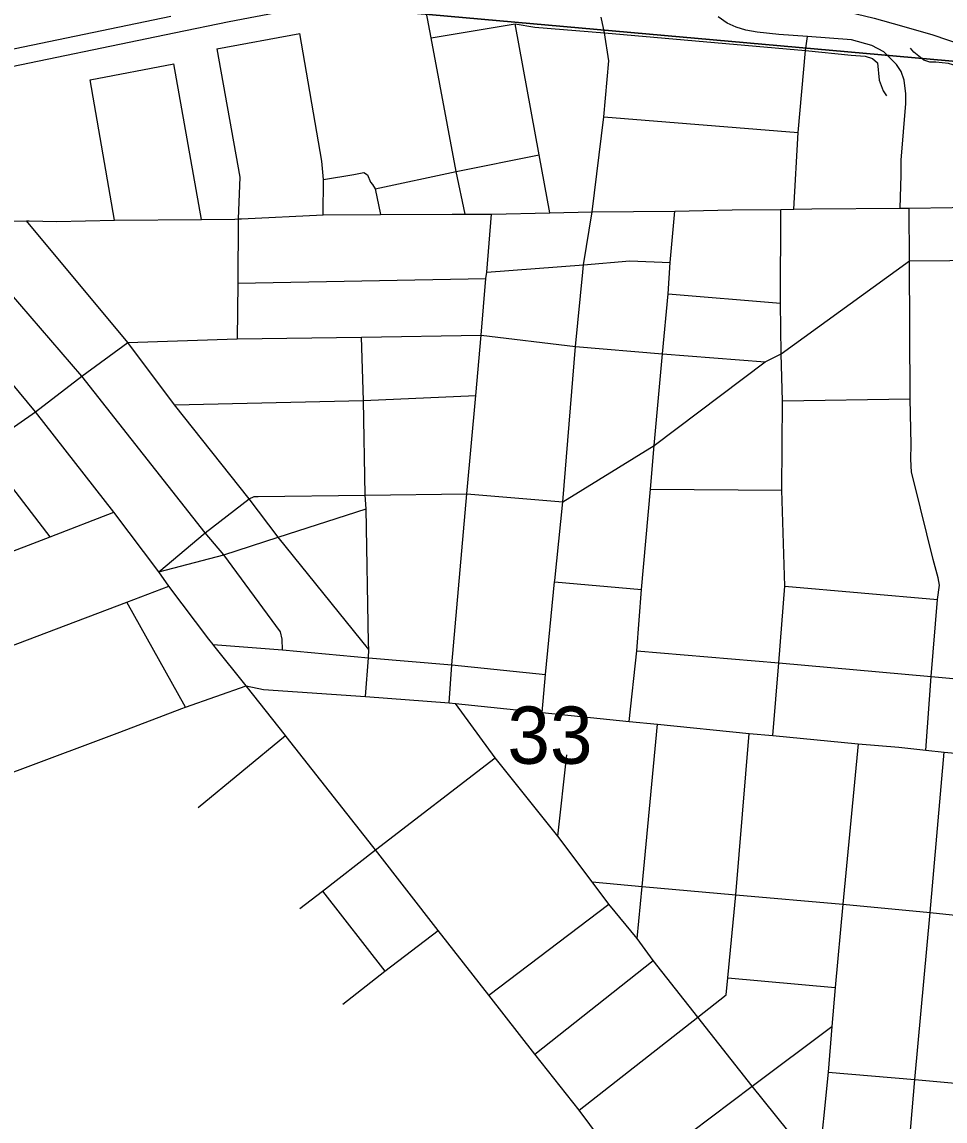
# Model space of a CAD drawing. Extents: x 0 to 34, y 0 to 22.
# Drawn here: x 7.163 to 7.838, y 17.141 to 17.945 of the extents above; entities that cross this region are included whole.
import ezdxf

# ---------------------------------------------------------------- set-up
doc = ezdxf.new("R2010")
doc.units = 0
for name, color, linetype in [('GM_X_City_Street', 7, 'Continuous'), ('GM_X_County_Road', 7, 'Continuous'), ('GM_X_Interchange_Ramps', 7, 'Continuous'), ('GM_X_Section', 7, 'Continuous'), ('GM_X_Section_Text', 7, 'Continuous'), ('GM_X_US_Route', 7, 'Continuous')]:
    doc.layers.add(name, color=color, linetype=linetype)

msp = doc.modelspace()

# ---------------------------------------------------------------- linework, layer by layer
at = {"layer": 'GM_X_City_Street'}
for p, q in [((7.46252, 17.9333), (7.52406, 17.94364)), ((7.30568, 17.9252), (7.36649, 17.93648)), ((7.21318, 17.90251), (7.27426, 17.91424)), ((7.29468, 17.80058), (7.27426, 17.91424)), ((7.23089, 17.80003), (7.21318, 17.90251)), ((7.58879, 17.8755), (7.73077, 17.864)), ((7.42167, 17.82297), (7.42544, 17.80408)), ((7.32108, 17.75385), (7.50248, 17.75728)), ((7.56802, 17.70757), (7.57337, 17.76184)), ((7.63591, 17.74599), (7.71793, 17.7393)), ((7.2748, 17.66502), (7.41293, 17.66811)), ((7.41293, 17.66811), (7.49506, 17.67184)), ((7.71933, 17.66783), (7.8128, 17.66936)), ((7.62291, 17.60322), (7.71884, 17.60241)), ((7.55277, 17.53556), (7.61633, 17.52978)), ((7.72124, 17.5324), (7.8328, 17.52257)), ((7.28296, 17.44379), (7.24005, 17.52068)), ((7.29211, 17.37039), (7.35591, 17.42305)), ((7.55509, 17.34949), (7.56165, 17.40891)), ((7.38298, 17.3093), (7.42867, 17.25078)), ((7.50467, 17.23324), (7.59254, 17.29971)), ((7.5382, 17.18996), (7.62474, 17.25859)), ((7.67948, 17.24574), (7.75806, 17.23874)), ((7.57073, 17.14902), (7.65761, 17.21715))]:
    msp.add_line(p, q, dxfattribs=at)
for points in [[(7.46252, 17.9333), (7.4561, 17.96686), (7.45379, 17.97877), (7.44997, 17.9984), (7.44721, 18.01417), (7.44531, 18.02426)], [(7.80538, 17.80878), (7.80621, 17.83295), (7.80621, 17.84384), (7.80957, 17.88531), (7.80957, 17.89243), (7.80831, 17.90248), (7.80621, 17.90877), (7.80286, 17.9138), (7.79365, 17.92301), (7.78485, 17.92762), (7.76978, 17.9318), (7.73763, 17.93425), (7.71676, 17.93583), (7.701, 17.93758), (7.69263, 17.93894), (7.68562, 17.94108), (7.67901, 17.944), (7.67239, 17.94867)], [(7.54941, 17.80535), (7.54144, 17.84781), (7.52406, 17.94364)], [(7.52406, 17.94364), (7.53837, 17.94111), (7.58916, 17.93702), (7.73634, 17.92397), (7.76975, 17.92069), (7.77996, 17.91987), (7.78527, 17.91824), (7.78895, 17.91497), (7.79017, 17.90231), (7.79303, 17.89455), (7.79548, 17.89088)], [(7.58031, 17.8061), (7.58879, 17.8755), (7.59247, 17.91639), (7.58916, 17.93702), (7.58695, 17.94845)], [(7.38362, 17.80384), (7.38388, 17.8297), (7.38267, 17.84304), (7.36649, 17.93648)], [(7.48742, 17.80436), (7.48084, 17.83559), (7.46252, 17.9333)], [(7.72768, 17.808), (7.73077, 17.864), (7.73634, 17.92397), (7.73763, 17.93425)], [(7.30568, 17.9252), (7.32261, 17.83148), (7.32143, 17.80086)], [(7.86381, 17.69887), (7.87137, 17.77071), (7.87505, 17.80972), (7.88239, 17.88126), (7.88337, 17.88811), (7.88092, 17.893), (7.84718, 17.91256), (7.84082, 17.91452), (7.83153, 17.91549), (7.82713, 17.91549), (7.82273, 17.91696), (7.8154, 17.92283), (7.81295, 17.92577)], [(7.38388, 17.8297), (7.40594, 17.83339), (7.41329, 17.83482), (7.41594, 17.83318), (7.41819, 17.82787), (7.41962, 17.82604), (7.42167, 17.82297), (7.48084, 17.83559), (7.54144, 17.84781)], [(7.18387, 17.56848), (7.15341, 17.6082), (7.13651, 17.6345), (7.10592, 17.68428), (7.07085, 17.73208), (7.03617, 17.77345), (7.00149, 17.81483)], [(7.14881, 17.79915), (7.16667, 17.79945), (7.16858, 17.79948), (7.18856, 17.79912), (7.23089, 17.80003), (7.29468, 17.80058), (7.31905, 17.80076), (7.32143, 17.80086), (7.32381, 17.80095), (7.38362, 17.80384), (7.42544, 17.80408), (7.47795, 17.80439), (7.48742, 17.80436), (7.50651, 17.80431), (7.54941, 17.80535), (7.58031, 17.8061), (7.64081, 17.80651), (7.68251, 17.8076), (7.71824, 17.8078)], [(7.47559, 17.4469), (7.47759, 17.47473), (7.48864, 17.59981), (7.49506, 17.67184), (7.49898, 17.71583), (7.50248, 17.75728), (7.5031, 17.76188), (7.50651, 17.80431)], [(7.57337, 17.76184), (7.57391, 17.76727), (7.58031, 17.8061)], [(7.60729, 17.43335), (7.61303, 17.48505), (7.61633, 17.52978), (7.62291, 17.60322), (7.62551, 17.63524), (7.63176, 17.70226), (7.63591, 17.74599), (7.63732, 17.76904), (7.64081, 17.80651)], [(7.71235, 17.42301), (7.71674, 17.4762), (7.72124, 17.5324), (7.71884, 17.60241), (7.71933, 17.66783), (7.71851, 17.70226), (7.71793, 17.7393), (7.71824, 17.8078)], [(7.71824, 17.8078), (7.72768, 17.808), (7.74088, 17.80828), (7.80538, 17.80878), (7.812, 17.80884), (7.87505, 17.80972), (7.94642, 17.81094), (7.94839, 17.81093)], [(7.82422, 17.41246), (7.82824, 17.46632), (7.8328, 17.52257), (7.83432, 17.53295), (7.83322, 17.53842), (7.82958, 17.55192), (7.81572, 17.60808), (7.81389, 17.61575), (7.81317, 17.62523), (7.81353, 17.6358), (7.8128, 17.66936), (7.81235, 17.77012), (7.812, 17.80884)], [(7.41682, 17.48592), (7.35067, 17.56822), (7.32944, 17.59624), (7.2748, 17.66502), (7.24065, 17.71047), (7.16667, 17.79945)], [(7.32143, 17.80086), (7.32108, 17.75385), (7.32074, 17.71318)], [(7.35387, 17.4857), (7.35344, 17.49365), (7.35223, 17.4989), (7.3109, 17.55525), (7.29727, 17.57122), (7.20704, 17.6858), (7.13136, 17.77365)], [(7.1731, 17.65979), (7.20704, 17.6858), (7.24065, 17.71047), (7.32074, 17.71318), (7.41163, 17.71436), (7.49898, 17.71583), (7.56802, 17.70757), (7.63176, 17.70226), (7.70671, 17.69636), (7.71851, 17.70226), (7.81235, 17.77012), (7.87137, 17.77071), (7.94278, 17.77012), (7.98645, 17.77131)], [(7.5031, 17.76188), (7.57391, 17.76727), (7.60785, 17.77015), (7.63732, 17.76904)], [(7.41674, 17.49082), (7.41496, 17.58885), (7.41423, 17.59884), (7.41293, 17.66811), (7.41163, 17.71436)], [(7.55287, 17.53652), (7.55878, 17.5941), (7.56802, 17.70757)], [(7.48864, 17.59981), (7.55878, 17.5941), (7.62551, 17.63524), (7.70671, 17.69636)], [(7.04388, 17.56226), (7.13651, 17.6345), (7.1731, 17.65979)], [(7.26332, 17.54277), (7.29727, 17.57122), (7.32944, 17.59624), (7.33301, 17.59786), (7.33605, 17.5979)], [(7.33605, 17.5979), (7.41423, 17.59884), (7.48864, 17.59981)], [(7.26332, 17.54277), (7.3109, 17.55525), (7.35067, 17.56822), (7.41496, 17.58885)], [(7.00845, 17.50268), (7.0707, 17.52621), (7.10689, 17.53887), (7.18387, 17.56848), (7.23044, 17.58639)], [(6.87492, 17.38734), (6.99726, 17.43179), (7.1298, 17.47903), (7.24005, 17.52068), (7.2707, 17.53226)], [(7.54373, 17.4399), (7.5462, 17.46772), (7.55277, 17.53556), (7.55287, 17.53652)], [(7.41443, 17.4515), (7.41661, 17.48), (7.41682, 17.48592), (7.41674, 17.49082)], [(7.30298, 17.48966), (7.35387, 17.4857), (7.41661, 17.48), (7.47759, 17.47473), (7.5462, 17.46772)], [(7.61303, 17.48505), (7.71674, 17.4762), (7.82824, 17.46632), (7.92133, 17.45769), (7.9884, 17.45125), (8.03565, 17.44612)], [(7.28023, 17.44275), (7.28296, 17.44379), (7.32712, 17.45947)], [(7.32712, 17.45947), (7.33979, 17.45676), (7.41443, 17.4515), (7.47559, 17.4469), (7.48027, 17.44644), (7.54373, 17.4399), (7.60729, 17.43335), (7.62802, 17.43128), (7.69497, 17.4246), (7.71235, 17.42301), (7.77465, 17.41698), (7.80455, 17.41459), (7.82422, 17.41246), (7.83759, 17.411), (7.90424, 17.40487), (7.96746, 17.39933), (7.98396, 17.39788), (8.02668, 17.39349)], [(6.83998, 17.31095), (6.86288, 17.30834), (6.89878, 17.30837), (6.91711, 17.31242), (6.95213, 17.32343), (7.02775, 17.35056), (7.15989, 17.39759), (7.23474, 17.42553), (7.28023, 17.44275)], [(7.74582, 17.10655), (7.72338, 17.13426), (7.69725, 17.16653), (7.65761, 17.21715), (7.62474, 17.25859), (7.61315, 17.27463), (7.59254, 17.29971), (7.58023, 17.31598), (7.55509, 17.34949), (7.50926, 17.40665), (7.48027, 17.44644)], [(7.61315, 17.27463), (7.61672, 17.31266), (7.62802, 17.43128)], [(7.65761, 17.21715), (7.67821, 17.23331), (7.67948, 17.24574), (7.68523, 17.30666), (7.69497, 17.4246)], [(7.77465, 17.41698), (7.76349, 17.29985), (7.75806, 17.23874), (7.75554, 17.21033), (7.75285, 17.17688), (7.74582, 17.10655), (7.74198, 17.04901), (7.74065, 17.03371), (7.7388, 17.01252), (7.73539, 16.97335)], [(7.79013, 16.92089), (7.79727, 16.98814), (7.80529, 17.04266), (7.81622, 17.17162), (7.82746, 17.29367), (7.83759, 17.411)], [(7.36655, 17.29647), (7.38298, 17.3093), (7.42178, 17.33945), (7.50926, 17.40665)], [(7.58023, 17.31598), (7.61672, 17.31266), (7.68523, 17.30666), (7.76349, 17.29985), (7.82746, 17.29367), (7.89175, 17.28681), (7.95662, 17.28109), (8.02011, 17.27567)], [(7.39787, 17.22664), (7.42867, 17.25078), (7.46774, 17.28045)], [(7.60801, 17.09936), (7.69725, 17.16653), (7.75554, 17.21033)], [(7.75285, 17.17688), (7.81622, 17.17162), (7.88056, 17.16566), (7.94565, 17.16006), (8.00914, 17.15479)]]:
    msp.add_lwpolyline(points, dxfattribs=at)
at = {"layer": 'GM_X_County_Road'}
for p, q in [((7.32712, 17.45947), (7.3036, 17.48888)), ((7.41993, 17.34179), (7.35652, 17.42227))]:
    msp.add_line(p, q, dxfattribs=at)
for points in [[(7.3036, 17.48888), (7.30298, 17.48966), (7.2998, 17.49363), (7.2707, 17.53226), (7.26332, 17.54277), (7.23044, 17.58639), (7.1731, 17.65979), (7.13331, 17.70789), (7.10111, 17.74736)], [(7.35652, 17.42227), (7.35591, 17.42305), (7.32712, 17.45947)], [(7.81694, 16.90102), (7.80727, 16.9044), (7.79013, 16.92089), (7.77348, 16.93625), (7.73539, 16.97335), (7.73247, 16.97619), (7.67406, 17.03219), (7.64779, 17.05836), (7.61492, 17.09112), (7.60801, 17.09936), (7.58641, 17.12811), (7.57073, 17.14902), (7.5382, 17.18996), (7.50467, 17.23324), (7.46774, 17.28045), (7.42178, 17.33945), (7.41993, 17.34179)]]:
    msp.add_lwpolyline(points, dxfattribs=at)
at = {"layer": 'GM_X_Interchange_Ramps'}
msp.add_lwpolyline([(7.75287, 17.96574), (7.75179, 17.95558), (7.76727, 17.95243), (7.78643, 17.94771), (7.80637, 17.94219), (7.82946, 17.93563), (7.8515, 17.92802), (7.88037, 17.91674), (7.9213, 17.90047), (7.94597, 17.89102), (7.94702, 17.8907)], dxfattribs=at)
at = {"layer": 'GM_X_Section'}
for points in [[(7.19193, 18.99089), (8.1916, 18.90176), (8.0955, 17.8939), (7.09659, 17.98301)], [(7.09659, 17.98301), (8.0955, 17.8939), (8.00161, 16.88676), (7.0031, 16.97632)]]:
    msp.add_lwpolyline(points, close=True, dxfattribs=at)
at = {"layer": 'GM_X_US_Route'}
for points in [[(7.10656, 17.90224), (7.13565, 17.90825), (7.27458, 17.93701), (7.31485, 17.9453), (7.3534, 17.95254), (7.39249, 17.95846), (7.41732, 17.96186)], [(6.39329, 17.79601), (6.43015, 17.80661), (6.46061, 17.8143), (6.49135, 17.8215), (6.52861, 17.8279), (6.57352, 17.83427), (6.62449, 17.84), (6.66108, 17.84281), (6.75463, 17.85058), (6.79575, 17.85487), (6.8304, 17.85948), (6.86264, 17.86452), (6.92714, 17.87707), (6.9432, 17.8806), (6.99343, 17.89069), (6.99968, 17.89194), (7.07496, 17.90827), (7.13226, 17.92013), (7.27206, 17.94906)]]:
    msp.add_lwpolyline(points, dxfattribs=at)

# ---------------------------------------------------------------- texts
at = {"layer": 'GM_X_Section_Text'}
msp.add_text('33', height=0.041856, rotation=0.00001, dxfattribs=at).set_placement((7.51826, 17.40242))

doc.saveas('drawing.dxf')
